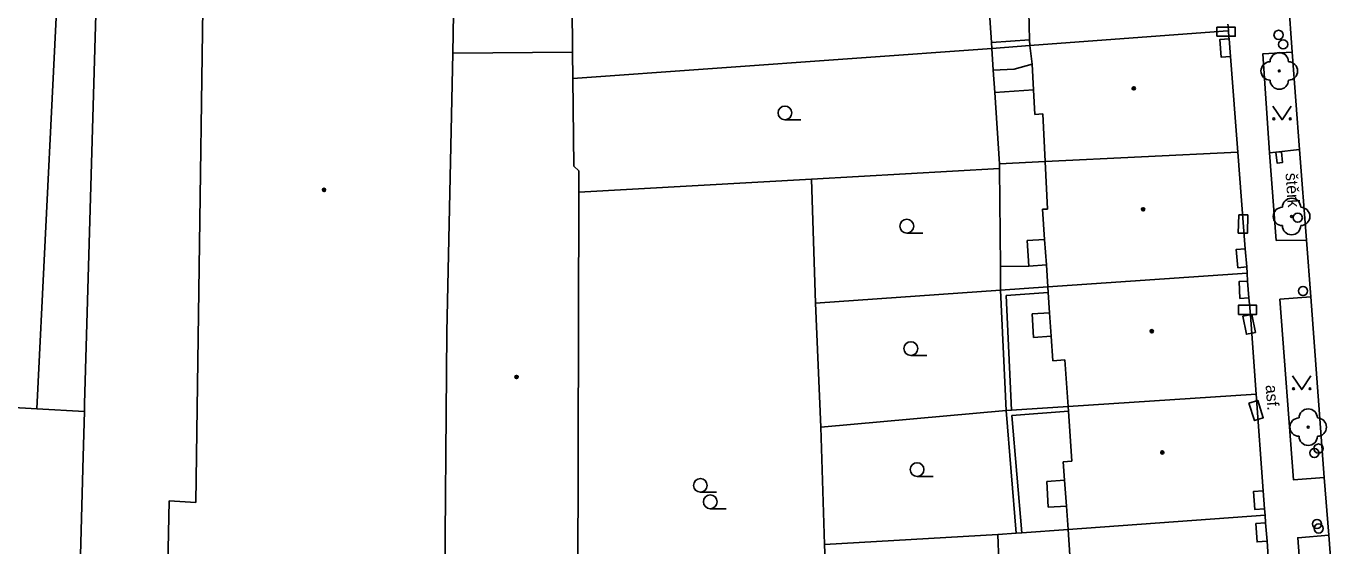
# Model space of a CAD drawing. Extents: x -596229 to -595156, y -1161237 to -1159376.
# Drawn here: x -596158.4 to -596087.1, y -1160989.5 to -1160961.1 of the extents above; entities that cross this region are included whole.
import ezdxf

# ---------------------------------------------------------------- set-up
doc = ezdxf.new("R2010")
doc.units = 0
for name, color, linetype in [('DOP - budovy nerozlisene - VP', 7, 'Continuous'), ('DOP - kresba z DSPS bez souradnic', 7, 'Continuous'), ('DOP - rozhrani ploch obecne', 7, 'Continuous'), ('Level 22', 7, 'Continuous'), ('Level 24', 7, 'Continuous'), ('Level 26', 7, 'Continuous'), ('Level 36', 7, 'Continuous'), ('Level 39', 7, 'Continuous'), ('slaboproud - povrch.  znaky a tel. budka skut. velikost', 7, 'Continuous'), ('TM - budovy zdene_ betonove - NP', 7, 'Continuous'), ('TM - budovy zdene_ betonove - VP', 7, 'Continuous'), ('TM - chodniky - VP', 7, 'Continuous'), ('TM - komunikace - VP', 7, 'Continuous'), ('TM - podezdivka plotu - VP', 7, 'Continuous'), ('TM - popis povrchu', 7, 'Continuous'), ('TM - rozhrani ploch obecne - VP', 7, 'Continuous')]:
    doc.layers.add(name, color=color, linetype=linetype)

msp = doc.modelspace()

# ---------------------------------------------------------------- linework, layer by layer
at = {"layer": 'DOP - budovy nerozlisene - VP'}
for points in [[(-596154.63, -1160917.46), (-596157.82, -1160981.98)], [(-596149.13, -1160987.09), (-596148.57, -1160947.24)], [(-596134.84, -1160947.49), (-596135.09, -1160962.55)], [(-596135.09, -1160962.55), (-596135.42, -1160977.79)], [(-596135.09, -1160962.55), (-596128.55, -1160962.5)], [(-596128.55, -1160962.5), (-596128.54, -1160963.93)], [(-596128.54, -1160963.93), (-596128.49, -1160968.72)], [(-596135.42, -1160977.79), (-596135.54, -1160993.38)], [(-596166.31, -1160981.48), (-596157.82, -1160981.98)], [(-596150.71, -1160993.14), (-596150.59, -1160987)], [(-596150.59, -1160987), (-596149.13, -1160987.09)]]:
    msp.add_lwpolyline(points, dxfattribs=at)
at = {"layer": 'DOP - kresba z DSPS bez souradnic'}
for points in [[(-596105.67, -1160961.96), (-596103.58, -1160961.82)], [(-596103.45, -1160963.14), (-596104.43, -1160963.42)], [(-596104.43, -1160963.42), (-596105.57, -1160963.47)], [(-596103.37, -1160964.56), (-596105.48, -1160964.7)], [(-596103.71, -1160972.78), (-596102.76, -1160972.72)], [(-596103.62, -1160974.18), (-596103.71, -1160972.78)], [(-596103.62, -1160974.18), (-596105.17, -1160974.2)], [(-596102.66, -1160974.12), (-596103.62, -1160974.18)], [(-596102.56, -1160975.62), (-596104.86, -1160975.78)], [(-596104.86, -1160975.78), (-596104.57, -1160982.05)], [(-596103.45, -1160976.79), (-596102.49, -1160976.73)], [(-596103.37, -1160978.08), (-596103.45, -1160976.79)], [(-596102.4, -1160978.01), (-596103.37, -1160978.08)], [(-596101.46, -1160982.1), (-596104.55, -1160982.34)], [(-596104.55, -1160982.34), (-596104.01, -1160988.76)], [(-596102.64, -1160985.95), (-596101.67, -1160985.88)], [(-596102.56, -1160987.36), (-596102.64, -1160985.95)], [(-596101.57, -1160987.3), (-596102.56, -1160987.36)]]:
    msp.add_lwpolyline(points, dxfattribs=at)
at = {"layer": 'DOP - rozhrani ploch obecne'}
for points in [[(-596155.21, -1160981.71), (-596152.77, -1160897.86)], [(-596105.67, -1160961.96), (-596106.07, -1160956.03)], [(-596128.59, -1160957.24), (-596128.55, -1160962.5)], [(-596128.54, -1160963.93), (-596105.65, -1160962.3)], [(-596105.65, -1160962.3), (-596105.67, -1160961.96)], [(-596105.65, -1160962.3), (-596103.57, -1160962.13)], [(-596105.57, -1160963.47), (-596105.65, -1160962.3)], [(-596105.48, -1160964.7), (-596105.57, -1160963.47)], [(-596105.22, -1160968.59), (-596105.48, -1160964.7)], [(-596115.5, -1160969.43), (-596105.22, -1160968.85)], [(-596105.22, -1160968.59), (-596102.73, -1160968.47)], [(-596105.22, -1160968.85), (-596105.22, -1160968.59)], [(-596105.22, -1160968.85), (-596105.17, -1160974.2)], [(-596128.21, -1160970.14), (-596115.5, -1160969.43)], [(-596115.27, -1160976.2), (-596115.5, -1160969.43)], [(-596105.17, -1160974.2), (-596105.17, -1160975.5)], [(-596102.58, -1160975.32), (-596105.17, -1160975.5)], [(-596105.17, -1160975.5), (-596115.27, -1160976.2)], [(-596104.87, -1160982.07), (-596105.17, -1160975.5)], [(-596115.27, -1160976.2), (-596114.99, -1160982.98)], [(-596155.21, -1160981.71), (-596155.22, -1160982.13)], [(-596157.82, -1160981.98), (-596155.22, -1160982.13)], [(-596155.29, -1160984.59), (-596155.22, -1160982.13)], [(-596104.87, -1160982.07), (-596114.99, -1160982.98)], [(-596104.57, -1160982.05), (-596104.87, -1160982.07)], [(-596104.31, -1160988.78), (-596104.87, -1160982.07)], [(-596101.48, -1160981.85), (-596104.57, -1160982.05)], [(-596114.99, -1160982.98), (-596114.79, -1160989.39)], [(-596155.68, -1160998.75), (-596155.29, -1160984.59)], [(-596114.79, -1160989.39), (-596105.31, -1160988.85)], [(-596105.31, -1160988.85), (-596104.31, -1160988.78)], [(-596105.31, -1160988.85), (-596105.26, -1160990.31)], [(-596104.31, -1160988.78), (-596104.01, -1160988.76)], [(-596104.01, -1160988.76), (-596101.48, -1160988.58)], [(-596114.51, -1160996.22), (-596114.79, -1160989.39)]]:
    msp.add_lwpolyline(points, dxfattribs=at)
at = {"layer": 'Level 22'}
for centre in [(-596089.94, -1160963.52), (-596089.27, -1160971.47), (-596088.36, -1160982.98)]:
    msp.add_circle(centre, 0.05, dxfattribs=at)
for centre, start, end in [((-596089.94, -1160963.02), 0, 180), ((-596090.44, -1160963.52), 90, 270), ((-596089.44, -1160963.52), 270, 90), ((-596089.94, -1160964.02), 180, 0), ((-596089.77, -1160971.47), 90, 270), ((-596089.27, -1160970.97), 0, 180), ((-596088.77, -1160971.47), 270, 90), ((-596089.27, -1160971.97), 180, 0), ((-596088.86, -1160982.98), 90, 270), ((-596088.36, -1160982.48), 0, 180), ((-596087.86, -1160982.98), 270, 90), ((-596088.36, -1160983.48), 180, 0)]:
    msp.add_arc(centre, 0.5, start, end, dxfattribs=at)
at = {"layer": 'Level 24'}
for points in [[(-596093.347, -1160961.628), (-596092.347, -1160961.628), (-596092.347, -1160961.128), (-596093.347, -1160961.128)], [(-596092.159, -1160971.377), (-596092.179, -1160972.377), (-596091.68, -1160972.387), (-596091.659, -1160971.387)], [(-596092.177, -1160976.818), (-596091.177, -1160976.818), (-596091.177, -1160976.318), (-596092.177, -1160976.318)], [(-596091.931, -1160976.921), (-596091.733, -1160977.901), (-596091.243, -1160977.802), (-596091.441, -1160976.822)], [(-596091.597, -1160981.672), (-596091.29, -1160982.624), (-596090.814, -1160982.47), (-596091.121, -1160981.518)]]:
    msp.add_lwpolyline(points, close=True, dxfattribs=at)
at = {"layer": 'Level 26'}
for centre in [(-596089.98, -1160961.55), (-596089.73, -1160962.07), (-596088.93, -1160971.54), (-596088.64, -1160975.54), (-596087.8, -1160984.15), (-596088.02, -1160984.39), (-596087.88, -1160988.27), (-596087.79, -1160988.52)]:
    msp.add_circle(centre, 0.25, dxfattribs=at)
at = {"layer": 'Level 36'}
for p, q in [((-596116.95, -1160966.185), (-596116.075, -1160966.185)), ((-596110.29, -1160972.375), (-596109.415, -1160972.375)), ((-596110.07, -1160979.065), (-596109.195, -1160979.065)), ((-596109.73, -1160985.675), (-596108.855, -1160985.675)), ((-596121.57, -1160986.535), (-596120.695, -1160986.535)), ((-596121.03, -1160987.435), (-596120.155, -1160987.435))]:
    msp.add_line(p, q, dxfattribs=at)
for points in [[(-596090.29, -1160965.44), (-596089.79, -1160966.19), (-596089.29, -1160965.44)], [(-596089.21, -1160980.18), (-596088.71, -1160980.93), (-596088.21, -1160980.18)]]:
    msp.add_lwpolyline(points, dxfattribs=at)
for centre, radius in [((-596116.95, -1160965.81), 0.375), ((-596090.24, -1160966.14), 0.05), ((-596089.341, -1160966.14), 0.05), ((-596110.29, -1160972), 0.375), ((-596110.07, -1160978.69), 0.375), ((-596089.16, -1160980.88), 0.05), ((-596088.261, -1160980.88), 0.05), ((-596109.73, -1160985.3), 0.375), ((-596121.57, -1160986.16), 0.375), ((-596121.03, -1160987.06), 0.375)]:
    msp.add_circle(centre, radius, dxfattribs=at)
at = {"layer": 'Level 39'}
for centre, radius in [((-596097.89, -1160964.47), 0.09), ((-596097.89, -1160964.47), 0.0398), ((-596142.13, -1160970.02), 0.09), ((-596142.13, -1160970.02), 0.0398), ((-596097.38, -1160971.08), 0.09), ((-596097.38, -1160971.08), 0.0398), ((-596096.91, -1160977.74), 0.09), ((-596096.91, -1160977.74), 0.0398), ((-596131.61, -1160980.24), 0.09), ((-596131.61, -1160980.24), 0.0398), ((-596096.33, -1160984.36), 0.09), ((-596096.33, -1160984.36), 0.0398)]:
    msp.add_circle(centre, radius, dxfattribs=at)
at = {"layer": 'slaboproud - povrch.  znaky a tel. budka skut. velikost'}
for points in [[(-596089.82, -1160967.93), (-596089.77, -1160968.53), (-596090.06, -1160968.55), (-596090.12, -1160967.95)], [(-596090.12, -1160967.95), (-596089.82, -1160967.93)]]:
    msp.add_lwpolyline(points, dxfattribs=at)
at = {"layer": 'TM - budovy zdene_ betonove - NP'}
for points in [[(-596092.61, -1160962.73), (-596093.11, -1160962.77), (-596093.18, -1160961.8), (-596092.68, -1160961.77)], [(-596091.72, -1160974.23), (-596092.2, -1160974.27), (-596092.29, -1160973.27), (-596091.8, -1160973.23)], [(-596091.6, -1160975.92), (-596092.09, -1160975.95), (-596092.14, -1160975.03), (-596091.67, -1160975)], [(-596090.75, -1160987.44), (-596091.28, -1160987.48), (-596091.35, -1160986.5), (-596090.82, -1160986.46)], [(-596090.61, -1160989.21), (-596091.15, -1160989.25), (-596091.22, -1160988.25), (-596090.69, -1160988.21)]]:
    msp.add_lwpolyline(points, dxfattribs=at)
at = {"layer": 'TM - budovy zdene_ betonove - VP'}
for points in [[(-596103.58, -1160961.82), (-596103.62, -1160960.29)], [(-596092.75, -1160960.97), (-596092.74, -1160961.07), (-596092.72, -1160961.33)], [(-596103.57, -1160962.13), (-596103.58, -1160961.82)], [(-596103.57, -1160962.13), (-596093.01, -1160961.35)], [(-596093.01, -1160961.35), (-596092.72, -1160961.33)], [(-596092.72, -1160961.33), (-596092.69, -1160961.67), (-596092.68, -1160961.77)], [(-596092.68, -1160961.77), (-596092.61, -1160962.73)], [(-596103.45, -1160963.14), (-596103.57, -1160962.13)], [(-596103.37, -1160964.56), (-596103.45, -1160963.14)], [(-596092.61, -1160962.73), (-596092.2, -1160967.95)], [(-596103.29, -1160965.89), (-596103.37, -1160964.56)], [(-596102.86, -1160965.87), (-596103.29, -1160965.89)], [(-596102.73, -1160968.47), (-596102.86, -1160965.87)], [(-596102.73, -1160968.47), (-596092.2, -1160967.95)], [(-596092.2, -1160967.95), (-596091.8, -1160973.23)], [(-596102.6, -1160971.07), (-596102.73, -1160968.47)], [(-596102.87, -1160971.08), (-596102.6, -1160971.07)], [(-596102.76, -1160972.72), (-596102.87, -1160971.08)], [(-596102.66, -1160974.12), (-596102.76, -1160972.72)], [(-596091.8, -1160973.23), (-596091.72, -1160974.23)], [(-596102.58, -1160975.32), (-596102.66, -1160974.12)], [(-596091.7, -1160974.56), (-596102.58, -1160975.32)], [(-596091.72, -1160974.23), (-596091.7, -1160974.56)], [(-596091.7, -1160974.56), (-596091.67, -1160975)], [(-596102.56, -1160975.62), (-596102.58, -1160975.32)], [(-596091.67, -1160975), (-596091.6, -1160975.92)], [(-596102.49, -1160976.73), (-596102.56, -1160975.62)], [(-596091.6, -1160975.92), (-596091.57, -1160976.26), (-596091.52, -1160976.86), (-596091.2, -1160981.18)], [(-596102.4, -1160978.01), (-596102.49, -1160976.73)], [(-596102.31, -1160979.35), (-596102.4, -1160978.01)], [(-596101.66, -1160979.31), (-596102.31, -1160979.35)], [(-596101.48, -1160981.85), (-596101.66, -1160979.31)], [(-596091.2, -1160981.18), (-596101.48, -1160981.85)], [(-596091.2, -1160981.18), (-596090.82, -1160986.46)], [(-596101.46, -1160982.1), (-596101.48, -1160981.85)], [(-596101.28, -1160984.84), (-596101.46, -1160982.1)], [(-596101.74, -1160984.87), (-596101.28, -1160984.84)], [(-596101.67, -1160985.88), (-596101.74, -1160984.87)], [(-596101.57, -1160987.3), (-596101.67, -1160985.88)], [(-596090.82, -1160986.46), (-596090.75, -1160987.44)], [(-596101.48, -1160988.58), (-596101.57, -1160987.3)], [(-596090.75, -1160987.44), (-596090.72, -1160987.79)], [(-596101.48, -1160988.58), (-596090.72, -1160987.79)], [(-596090.72, -1160987.79), (-596090.69, -1160988.21)], [(-596090.69, -1160988.21), (-596090.61, -1160989.21)], [(-596101.38, -1160989.98), (-596101.48, -1160988.58)], [(-596090.61, -1160989.21), (-596090.59, -1160989.49), (-596090.54, -1160990.09), (-596090.19, -1160994.42)]]:
    msp.add_lwpolyline(points, dxfattribs=at)
at = {"layer": 'TM - chodniky - VP'}
for points in [[(-596090.48, -1160967.99), (-596090.83, -1160962.58), (-596089.23, -1160962.49)], [(-596088.46, -1160972.76), (-596090.11, -1160972.78), (-596090.48, -1160967.99)], [(-596088.22, -1160975.86), (-596089.91, -1160975.99), (-596089.16, -1160985.86), (-596087.48, -1160985.73)], [(-596087.24, -1160988.89), (-596088.93, -1160989.02), (-596088.14, -1160999.67), (-596086.44, -1160999.54)]]:
    msp.add_lwpolyline(points, dxfattribs=at)
at = {"layer": 'TM - komunikace - VP'}
for points in [[(-596089.44, -1160959.64), (-596089.23, -1160962.49)], [(-596089.23, -1160962.49), (-596088.83, -1160967.81)], [(-596088.83, -1160967.81), (-596088.46, -1160972.76)], [(-596088.46, -1160972.76), (-596088.22, -1160975.86)], [(-596088.22, -1160975.86), (-596087.48, -1160985.73)], [(-596087.48, -1160985.73), (-596087.24, -1160988.89)], [(-596087.24, -1160988.89), (-596086.44, -1160999.54)]]:
    msp.add_lwpolyline(points, dxfattribs=at)
at = {"layer": 'TM - podezdivka plotu - VP'}
for points in [[(-596128.2, -1160968.97), (-596128.49, -1160968.72)], [(-596128.21, -1160970.14), (-596128.2, -1160968.97)], [(-596128.27, -1160991.51), (-596128.21, -1160970.14)]]:
    msp.add_lwpolyline(points, dxfattribs=at)
at = {"layer": 'TM - rozhrani ploch obecne - VP'}
for points in [[(-596090.48, -1160967.99), (-596090.12, -1160967.95)], [(-596090.12, -1160967.95), (-596088.83, -1160967.81)]]:
    msp.add_lwpolyline(points, dxfattribs=at)

# ---------------------------------------------------------------- texts
at = {"layer": 'TM - popis povrchu'}
for s, rotation, p in [('štěrk', 274, (-596089.6, -1160969.11)), ('asf.', 274.25, (-596090.69, -1160980.69))]:
    msp.add_text(s, height=0.65, rotation=rotation, dxfattribs=at).set_placement(p)

doc.saveas('drawing.dxf')
